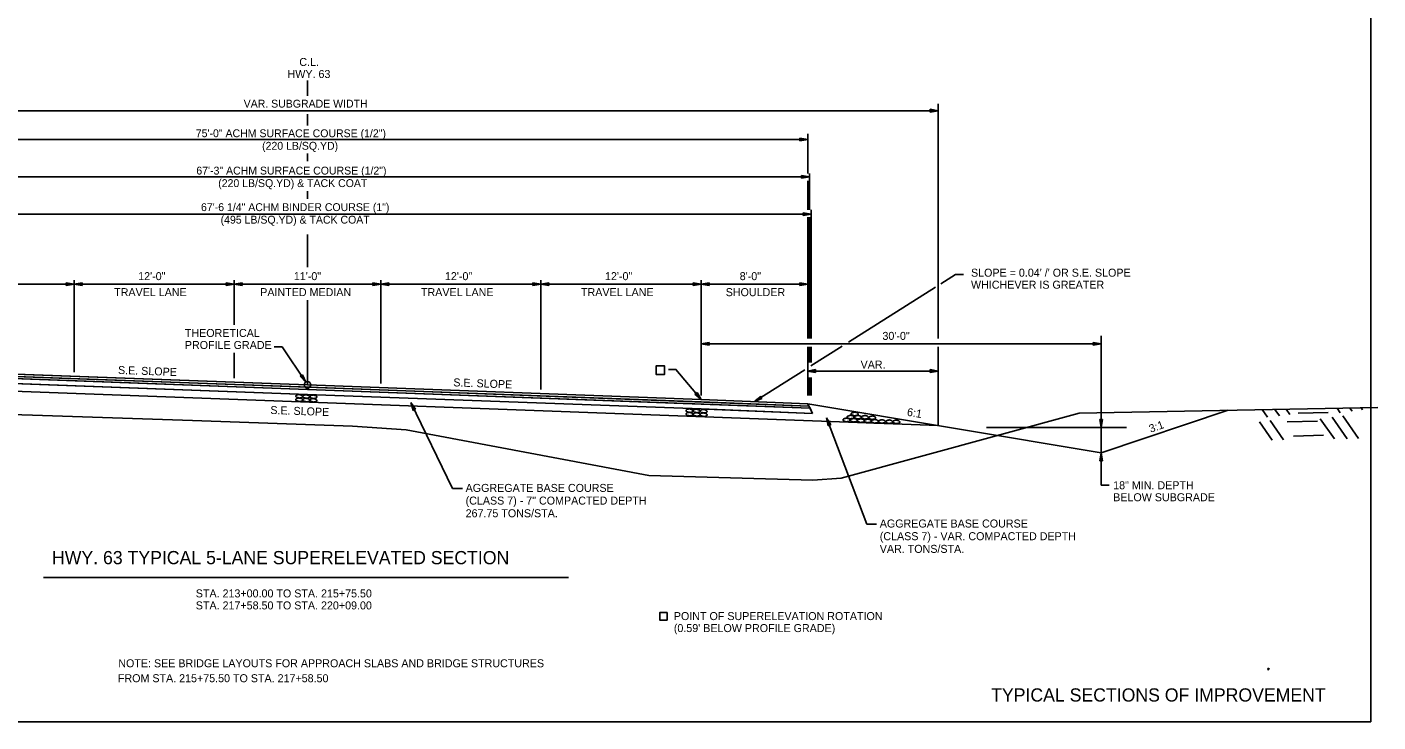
# Model space of a CAD drawing. Extents: x 1461846 to 1462006, y 1686171 to 1686805.
# Drawn here: x 1461905.1 to 1462006.4, y 1686568.7 to 1686620.8 of the extents above; entities that cross this region are included whole.
import ezdxf

# ---------------------------------------------------------------- set-up
doc = ezdxf.new("R2010")
doc.units = 0
for name, color, linetype in [('1', 7, 'Continuous'), ('10', 7, 'Continuous'), ('12', 7, 'Continuous'), ('19', 7, 'Continuous'), ('20', 7, 'Continuous'), ('3', 7, 'Continuous'), ('NO PLOT CELL', 7, 'Continuous'), ('R_Draft', 7, 'Continuous')]:
    doc.layers.add(name, color=color, linetype=linetype)

# ---------------------------------------------------------------- blocks, each defined once
blk = doc.blocks.new('ROCKS')
at = {"layer": '1'}
blk.add_spline([(0.013, 0.06), (0.053, 0.053), (0.107, 0.033), (0.133, 0.013), (0.133, -0.007), (0.12, -0.033), (0.107, -0.04), (0.073, -0.053), (0.033, -0.067), (0.013, -0.067), (-0.02, -0.06), (-0.06, -0.053), (-0.087, -0.047), (-0.113, -0.02), (-0.113, -0.007), (-0.107, 0.02), (-0.087, 0.033), (-0.067, 0.047), (-0.033, 0.053), (-0.02, 0.06), (0.013, 0.06)], degree=3, dxfattribs=at)

msp = doc.modelspace()

# ---------------------------------------------------------------- linework, layer by layer
at = {"layer": '10'}
for p, q in [((1462005.89, 1686568.71), (1462005.89, 1686666.54)), ((1461846.35, 1686568.71), (1462005.89, 1686568.71))]:
    msp.add_line(p, q, dxfattribs=at)
msp.add_lwpolyline([(1461952.31, 1686594.77), (1461952.95, 1686594.77), (1461952.95, 1686595.41), (1461952.31, 1686595.41), (1461952.31, 1686594.77)], dxfattribs=at)
at = {"layer": '19'}
for p, q in [((1461973.45, 1686597.47), (1461973.45, 1686615.07)), ((1461876.76, 1686614.55), (1461973.45, 1686614.55)), ((1461972.85, 1686614.45), (1461972.85, 1686614.66)), ((1461972.85, 1686614.66), (1461973.45, 1686614.55)), ((1461972.85, 1686614.6), (1461973.29, 1686614.57)), ((1461973.45, 1686614.55), (1461972.85, 1686614.45)), ((1461973.29, 1686614.54), (1461972.85, 1686614.5)), ((1461963.68, 1686609.84), (1461963.68, 1686612.81)), ((1461888.68, 1686612.38), (1461963.68, 1686612.38)), ((1461963.08, 1686612.28), (1461963.08, 1686612.49)), ((1461963.08, 1686612.49), (1461963.68, 1686612.38)), ((1461963.08, 1686612.43), (1461963.52, 1686612.4)), ((1461963.68, 1686612.38), (1461963.08, 1686612.28)), ((1461963.52, 1686612.37), (1461963.08, 1686612.33)), ((1461963.68, 1686607.11), (1461963.68, 1686609.29)), ((1461963.68, 1686597.47), (1461963.68, 1686606.56)), ((1461963.68, 1686593.19), (1461963.68, 1686596.83)), ((1461973.45, 1686590.94), (1461973.45, 1686596.83)), ((1461937.05, 1686586.22), (1461933.92, 1686592.66)), ((1461934.1, 1686592.07), (1461933.92, 1686592.66)), ((1461933.92, 1686592.66), (1461934.28, 1686592.17)), ((1461934.14, 1686592.1), (1461933.98, 1686592.51)), ((1461934, 1686592.52), (1461934.23, 1686592.15)), ((1461963.68, 1686592.57), (1461964.04, 1686591.84)), ((1461934.28, 1686592.17), (1461934.1, 1686592.07)), ((1461964.04, 1686591.84), (1461963.85, 1686592.23)), ((1461963.85, 1686592.23), (1461963.85, 1686592.23)), ((1461964.04, 1686591.84), (1461964.04, 1686591.84)), ((1461968.1, 1686583.55), (1461965.09, 1686591.52)), ((1461965.2, 1686590.92), (1461965.09, 1686591.52)), ((1461965.09, 1686591.52), (1461965.4, 1686590.99)), ((1461998.15, 1686591.56), (1461997.76, 1686592.13)), ((1461999.04, 1686591.67), (1461998.7, 1686592.15)), ((1461999.83, 1686591.77), (1461999.56, 1686592.16)), ((1462002.71, 1686591.91), (1462000.45, 1686591.86)), ((1462004.12, 1686589.95), (1462002.99, 1686591.56)), ((1462003.6, 1686591.9), (1462003.36, 1686592.24)), ((1462004.97, 1686589.96), (1462003.79, 1686591.66)), ((1462004.49, 1686592.01), (1462004.32, 1686592.25)), ((1462005.28, 1686592.12), (1462005.17, 1686592.27)), ((1461965.25, 1686590.94), (1461965.13, 1686591.36)), ((1461965.16, 1686591.37), (1461965.35, 1686590.98)), ((1461965.4, 1686590.99), (1461965.2, 1686590.92)), ((1461998.51, 1686589.85), (1461997.55, 1686591.21)), ((1461999.36, 1686589.86), (1461998.34, 1686591.32)), ((1462001.89, 1686591.27), (1461999.62, 1686591.21)), ((1462003.16, 1686589.93), (1462002.1, 1686591.45)), ((1462002.35, 1686590.21), (1462000.09, 1686590.14)), ((1461937.79, 1686586.22), (1461937.05, 1686586.22)), ((1461968.84, 1686583.55), (1461968.1, 1686583.55))]:
    msp.add_line(p, q, dxfattribs=at)
for points in [[(1461888.59, 1686595.2), (1461901.59, 1686594.72), (1461926.18, 1686593.81), (1461955.68, 1686592.72), (1461963.76, 1686592.4), (1461963.68, 1686592.57), (1461955.68, 1686592.89), (1461926.18, 1686593.98), (1461901.55, 1686594.89), (1461888.68, 1686595.37)], [(1461896.51, 1686594.74), (1461907.59, 1686594.33), (1461926.17, 1686593.65), (1461955.9, 1686592.55), (1461963.85, 1686592.23), (1461963.85, 1686592.23), (1461963.76, 1686592.4), (1461963.76, 1686592.4), (1461926.32, 1686593.81), (1461907.55, 1686594.5), (1461896.59, 1686594.91)]]:
    msp.add_lwpolyline(points, close=True, dxfattribs=at)
for points in [[(1461963.85, 1686592.23), (1461955.68, 1686592.55), (1461926.17, 1686593.65), (1461896.84, 1686594.73), (1461896.51, 1686594.74)], [(1461896.33, 1686594.38), (1461896.82, 1686594.36), (1461926.18, 1686593.27), (1461955.68, 1686592.18), (1461964.04, 1686591.84)]]:
    msp.add_lwpolyline(points, dxfattribs=at)
at = {"layer": '20'}
for p, q in [((1461926.18, 1686610.77), (1461926.18, 1686611.34)), ((1461963.8, 1686607.11), (1461963.8, 1686609.84)), ((1461963.8, 1686609.58), (1461896.55, 1686609.58)), ((1461963.2, 1686609.48), (1461963.2, 1686609.69)), ((1461963.2, 1686609.69), (1461963.8, 1686609.58)), ((1461963.2, 1686609.63), (1461963.64, 1686609.6)), ((1461963.8, 1686609.58), (1461963.2, 1686609.48)), ((1461963.64, 1686609.57), (1461963.2, 1686609.53)), ((1461926.18, 1686607.95), (1461926.18, 1686608.52)), ((1461963.93, 1686606.78), (1461896.41, 1686606.78)), ((1461963.33, 1686606.68), (1461963.33, 1686606.89)), ((1461963.33, 1686606.89), (1461963.93, 1686606.78)), ((1461963.33, 1686606.83), (1461963.77, 1686606.8)), ((1461963.93, 1686606.78), (1461963.33, 1686606.68)), ((1461963.77, 1686606.77), (1461963.33, 1686606.73)), ((1461963.93, 1686601.17), (1461963.93, 1686607.11)), ((1461963.8, 1686601.17), (1461963.8, 1686606.56)), ((1461963.8, 1686597.47), (1461963.8, 1686601.17)), ((1461963.93, 1686597.47), (1461963.93, 1686601.17)), ((1461963.8, 1686595.67), (1461963.8, 1686596.83)), ((1461963.93, 1686595.67), (1461963.93, 1686596.83)), ((1461964.27, 1686595.13), (1461963.67, 1686595.02)), ((1461963.67, 1686595.02), (1461973.45, 1686595.02)), ((1461963.67, 1686595.02), (1461964.27, 1686594.92)), ((1461963.8, 1686593.19), (1461963.8, 1686594.55)), ((1461964.27, 1686595.07), (1461963.83, 1686595.04)), ((1461963.83, 1686595.01), (1461964.27, 1686594.97)), ((1461963.93, 1686593.19), (1461963.93, 1686594.55)), ((1461964.27, 1686594.92), (1461964.27, 1686595.13)), ((1461972.85, 1686595.13), (1461972.85, 1686594.92)), ((1461973.45, 1686595.02), (1461972.85, 1686595.13)), ((1461973.29, 1686595.04), (1461972.85, 1686595.07)), ((1461972.85, 1686594.92), (1461973.45, 1686595.02)), ((1461972.85, 1686594.97), (1461973.29, 1686595.01))]:
    msp.add_line(p, q, dxfattribs=at)
at = {"layer": '3'}
msp.add_line((1461906.38, 1686579.55), (1461945.74, 1686579.55), dxfattribs=at)
at = {"layer": 'NO PLOT CELL'}
msp.add_circle((1461998.22, 1686572.68), 0.05, dxfattribs=at)
at = {"layer": 'R_Draft'}
for p, q in [((1461926.18, 1686615.67), (1461926.18, 1686616.81)), ((1461926.18, 1686613.45), (1461926.18, 1686614.28)), ((1461926.18, 1686602.81), (1461926.18, 1686605.27)), ((1461908.08, 1686601.64), (1461908.08, 1686601.43)), ((1461908.68, 1686601.54), (1461908.08, 1686601.64)), ((1461908.68, 1686594.93), (1461908.68, 1686601.84)), ((1461908.68, 1686601.54), (1461909.28, 1686601.64)), ((1461909.28, 1686601.64), (1461909.28, 1686601.43)), ((1461920.08, 1686601.64), (1461920.08, 1686601.43)), ((1461920.68, 1686601.54), (1461920.08, 1686601.64)), ((1461920.68, 1686598.48), (1461920.68, 1686601.84)), ((1461920.68, 1686601.54), (1461921.28, 1686601.64)), ((1461921.28, 1686601.64), (1461921.28, 1686601.43)), ((1461931.08, 1686601.64), (1461931.08, 1686601.43)), ((1461931.68, 1686601.54), (1461931.08, 1686601.64)), ((1461931.68, 1686594.08), (1461931.68, 1686601.84)), ((1461931.68, 1686601.54), (1461932.28, 1686601.64)), ((1461932.28, 1686601.64), (1461932.28, 1686601.43)), ((1461943.08, 1686601.64), (1461943.08, 1686601.43)), ((1461943.68, 1686601.54), (1461943.08, 1686601.64)), ((1461943.68, 1686593.63), (1461943.68, 1686601.84)), ((1461943.68, 1686601.54), (1461944.28, 1686601.64)), ((1461944.28, 1686601.64), (1461944.28, 1686601.43)), ((1461955.08, 1686601.43), (1461955.08, 1686601.64)), ((1461955.08, 1686601.64), (1461955.68, 1686601.54)), ((1461955.68, 1686593.19), (1461955.68, 1686601.84)), ((1461955.68, 1686601.54), (1461956.28, 1686601.64)), ((1461956.28, 1686601.64), (1461956.28, 1686601.43)), ((1461963.08, 1686601.43), (1461963.08, 1686601.64)), ((1461963.08, 1686601.64), (1461963.68, 1686601.54)), ((1461963.68, 1686597.47), (1461963.68, 1686601.84)), ((1461896.68, 1686601.54), (1461908.68, 1686601.54)), ((1461908.52, 1686601.55), (1461908.08, 1686601.59)), ((1461908.08, 1686601.43), (1461908.68, 1686601.54)), ((1461908.08, 1686601.48), (1461908.52, 1686601.52)), ((1461908.68, 1686601.54), (1461920.68, 1686601.54)), ((1461909.28, 1686601.43), (1461908.68, 1686601.54)), ((1461908.84, 1686601.55), (1461909.28, 1686601.59)), ((1461909.28, 1686601.48), (1461908.84, 1686601.52)), ((1461920.52, 1686601.55), (1461920.08, 1686601.59)), ((1461920.08, 1686601.43), (1461920.68, 1686601.54)), ((1461920.08, 1686601.48), (1461920.52, 1686601.52)), ((1461921.28, 1686601.43), (1461920.68, 1686601.54)), ((1461920.68, 1686601.54), (1461931.68, 1686601.54)), ((1461920.84, 1686601.55), (1461921.28, 1686601.59)), ((1461921.28, 1686601.48), (1461920.84, 1686601.52)), ((1461931.52, 1686601.55), (1461931.08, 1686601.59)), ((1461931.08, 1686601.43), (1461931.68, 1686601.54)), ((1461931.08, 1686601.48), (1461931.52, 1686601.52)), ((1461932.28, 1686601.43), (1461931.68, 1686601.54)), ((1461943.68, 1686601.54), (1461931.68, 1686601.54)), ((1461931.84, 1686601.55), (1461932.28, 1686601.59)), ((1461932.28, 1686601.48), (1461931.84, 1686601.52)), ((1461943.52, 1686601.55), (1461943.08, 1686601.59)), ((1461943.08, 1686601.43), (1461943.68, 1686601.54)), ((1461943.08, 1686601.48), (1461943.52, 1686601.52)), ((1461955.68, 1686601.54), (1461943.68, 1686601.54)), ((1461944.28, 1686601.43), (1461943.68, 1686601.54)), ((1461943.84, 1686601.55), (1461944.28, 1686601.59)), ((1461944.28, 1686601.48), (1461943.84, 1686601.52)), ((1461955.08, 1686601.59), (1461955.52, 1686601.55)), ((1461955.68, 1686601.54), (1461955.08, 1686601.43)), ((1461955.52, 1686601.52), (1461955.08, 1686601.48)), ((1461963.68, 1686601.54), (1461955.68, 1686601.54)), ((1461956.28, 1686601.43), (1461955.68, 1686601.54)), ((1461955.84, 1686601.55), (1461956.28, 1686601.59)), ((1461956.28, 1686601.48), (1461955.84, 1686601.52)), ((1461963.08, 1686601.59), (1461963.52, 1686601.55)), ((1461963.68, 1686601.54), (1461963.08, 1686601.43)), ((1461963.52, 1686601.52), (1461963.08, 1686601.48)), ((1461926.18, 1686593.98), (1461926.18, 1686600.34)), ((1461985.68, 1686590.73), (1461985.68, 1686597.66)), ((1461955.68, 1686597.06), (1461956.28, 1686597.17)), ((1461985.68, 1686597.06), (1461955.68, 1686597.06)), ((1461956.28, 1686596.96), (1461955.68, 1686597.06)), ((1461955.84, 1686597.08), (1461956.28, 1686597.11)), ((1461956.28, 1686597.01), (1461955.84, 1686597.05)), ((1461956.28, 1686597.17), (1461956.28, 1686596.96)), ((1461985.08, 1686596.96), (1461985.08, 1686597.17)), ((1461985.08, 1686597.17), (1461985.68, 1686597.06)), ((1461985.08, 1686597.11), (1461985.52, 1686597.08)), ((1461985.68, 1686597.06), (1461985.08, 1686596.96)), ((1461985.52, 1686597.05), (1461985.08, 1686597.01)), ((1461920.68, 1686594.48), (1461920.68, 1686596.38)), ((1461925.8, 1686594.75), (1461925.63, 1686594.63)), ((1461925.63, 1686594.63), (1461926.04, 1686594.19)), ((1461925.67, 1686594.66), (1461925.94, 1686594.32)), ((1461925.96, 1686594.33), (1461925.76, 1686594.72)), ((1461926.04, 1686594.19), (1461925.8, 1686594.75)), ((1461955.38, 1686593.42), (1461955.22, 1686593.29)), ((1461955.22, 1686593.29), (1461955.68, 1686592.89)), ((1461955.25, 1686593.31), (1461955.56, 1686593)), ((1461955.58, 1686593.02), (1461955.34, 1686593.38)), ((1461955.68, 1686592.89), (1461955.38, 1686593.42)), ((1461963.68, 1686592.57), (1461955.68, 1686592.89)), ((1461963.76, 1686592.4), (1461955.68, 1686592.72)), ((1461955.84, 1686592.55), (1461955.68, 1686592.55)), ((1461963.85, 1686592.23), (1461955.84, 1686592.55)), ((1461959.68, 1686592.73), (1461960.13, 1686593.14)), ((1461960.24, 1686592.96), (1461959.68, 1686592.73)), ((1461959.8, 1686592.83), (1461960.15, 1686593.09)), ((1461960.21, 1686593.01), (1461959.82, 1686592.8)), ((1461960.13, 1686593.14), (1461960.24, 1686592.96)), ((1461985.68, 1686588.9), (1461963.68, 1686592.57)), ((1461956.03, 1686592.16), (1461955.68, 1686592.18)), ((1461964.04, 1686591.84), (1461956.03, 1686592.16)), ((1461995.2, 1686592.08), (1461985.68, 1686588.9)), ((1461977.07, 1686590.78), (1461987.58, 1686590.78)), ((1461985.78, 1686591.38), (1461985.57, 1686591.38)), ((1461985.57, 1686591.38), (1461985.68, 1686590.78)), ((1461985.62, 1686591.38), (1461985.66, 1686590.94)), ((1461985.68, 1686590.78), (1461985.78, 1686591.38)), ((1461985.68, 1686586.46), (1461985.68, 1686590.73)), ((1461985.69, 1686590.94), (1461985.73, 1686591.38)), ((1461985.68, 1686588.9), (1461985.57, 1686588.3)), ((1461985.66, 1686588.74), (1461985.63, 1686588.3)), ((1461985.78, 1686588.3), (1461985.68, 1686588.9)), ((1461985.73, 1686588.3), (1461985.69, 1686588.74)), ((1461985.57, 1686588.3), (1461985.78, 1686588.3)), ((1461986.28, 1686586.46), (1461985.68, 1686586.46))]:
    msp.add_line(p, q, dxfattribs=at)
for points in [[(1461975.35, 1686602.27), (1461974.75, 1686602.27), (1461973.65, 1686601.57)], [(1461973.25, 1686601.32), (1461966.74, 1686597.2)], [(1461923.67, 1686596.85), (1461924.27, 1686596.85), (1461926.04, 1686594.19)], [(1461966.27, 1686596.9), (1461963.91, 1686595.41)], [(1461955.68, 1686592.89), (1461926.18, 1686593.98), (1461896.68, 1686595.07)], [(1461955.68, 1686592.72), (1461926.18, 1686593.81), (1461896.68, 1686594.9)], [(1461955.68, 1686592.55), (1461926.18, 1686593.65), (1461896.68, 1686594.74)], [(1461952.95, 1686594.77), (1461952.95, 1686595.41), (1461952.31, 1686595.41), (1461952.31, 1686594.77), (1461952.95, 1686594.77)], [(1461953.23, 1686595.15), (1461953.8, 1686595.15), (1461955.68, 1686592.89)], [(1461963.45, 1686595.12), (1461959.68, 1686592.73)], [(1461955.68, 1686592.18), (1461926.18, 1686593.27), (1461896.68, 1686594.36)], [(1461973.45, 1686590.94), (1461896.68, 1686593.78)], [(1462006.43, 1686592.29), (1461984.04, 1686591.86), (1461966.18, 1686586.99), (1461964.05, 1686586.83), (1461959.64, 1686586.97), (1461951.76, 1686587.2), (1461933.56, 1686590.62), (1461929.56, 1686590.9), (1461917.56, 1686591.31), (1461905.56, 1686591.72), (1461901.56, 1686591.84), (1461888.13, 1686588.11)], [(1461953.14, 1686576.35), (1461953.14, 1686576.91), (1461952.58, 1686576.91), (1461952.58, 1686576.35), (1461953.14, 1686576.35)]]:
    msp.add_lwpolyline(points, dxfattribs=at)
msp.add_circle((1461926.17, 1686593.98), 0.25, dxfattribs=at)

# ---------------------------------------------------------------- block references
at = {"layer": '19'}
for p, xscale, yscale, rotation in [((1461925.54, 1686593.14), 2.0611362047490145, 2.0611362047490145, -4.232447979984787), ((1461925.54, 1686592.88), 2.0611362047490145, 2.0611362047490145, -4.232447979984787), ((1461926.07, 1686593.12), 2.0611362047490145, 2.0611362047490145, -4.232447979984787), ((1461926.07, 1686592.86), 2.0611362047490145, 2.0611362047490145, -4.232447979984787), ((1461926.6, 1686593.1), 2.0611362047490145, 2.0611362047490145, -4.232447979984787), ((1461926.6, 1686592.84), 2.0611362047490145, 2.0611362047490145, -4.232447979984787), ((1461954.8, 1686591.8), 2.0611362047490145, 2.0611362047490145, -4.232447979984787), ((1461954.8, 1686592.06), 2.0611362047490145, 2.0611362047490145, -4.232447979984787), ((1461955.33, 1686591.78), 2.0611362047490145, 2.0611362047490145, -4.232447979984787), ((1461955.33, 1686592.04), 2.0611362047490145, 2.0611362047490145, -4.232447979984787), ((1461955.86, 1686592.02), 2.0611362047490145, 2.0611362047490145, -4.232447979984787), ((1461955.86, 1686591.76), 2.0611362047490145, 2.0611362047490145, -4.232447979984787), ((1461966.6, 1686591.36), 2.061136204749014, -2.061136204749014, 178.63717054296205), ((1461966.91, 1686591.58), 2.061136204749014, -2.061136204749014, 178.63717054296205), ((1461967.22, 1686591.81), 2.061136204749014, -2.061136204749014, 178.63717054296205), ((1461967.46, 1686591.57), 2.061136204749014, -2.061136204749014, 178.63717054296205), ((1461967.99, 1686591.56), 2.061136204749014, -2.061136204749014, 178.63717054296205), ((1461968.53, 1686591.53), 2.061136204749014, -2.061136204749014, 178.63717054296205), ((1461967.15, 1686591.34), 2.061136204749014, -2.061136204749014, 178.63717054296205), ((1461967.68, 1686591.31), 2.061136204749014, -2.061136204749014, 178.63717054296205), ((1461968.2, 1686591.29), 2.061136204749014, -2.061136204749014, 178.63717054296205), ((1461968.73, 1686591.26), 2.061136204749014, -2.061136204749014, 178.63717054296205), ((1461969.26, 1686591.25), 2.061136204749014, -2.061136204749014, 178.63717054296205), ((1461969.8, 1686591.23), 2.061136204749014, -2.061136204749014, 178.63717054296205), ((1461970.34, 1686591.22), 2.061136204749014, -2.061136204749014, 178.63717054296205)]:
    msp.add_blockref('ROCKS', p, dxfattribs=dict(at, xscale=xscale, yscale=yscale, rotation=rotation))

# ---------------------------------------------------------------- texts
at = {"layer": '10'}
for s, p in [('STA. 213+00.00 TO STA. 215+75.50', (1461917.8, 1686578.05)), ('STA. 217+58.50 TO STA. 220+09.00', (1461917.8, 1686577.15)), ('FROM STA. 215+75.50 TO STA. 217+58.50', (1461911.96, 1686571.69))]:
    msp.add_text(s, height=0.6, rotation=359.9954, dxfattribs=at).set_placement(p)
msp.add_text('NOTE: SEE BRIDGE LAYOUTS FOR APPROACH SLABS AND BRIDGE STRUCTURES', height=0.6, dxfattribs=at).set_placement((1461911.99, 1686572.81))
at = {"layer": '12'}
msp.add_text('HWY. 63 TYPICAL 5-LANE SUPERELEVATED SECTION', height=0.99, rotation=359.9954, dxfattribs=at).set_placement((1461907.02, 1686580.54))
at = {"layer": '19'}
for s, p in [('VAR. SUBGRADE WIDTH', (1461921.39, 1686614.78)), ('75\'-0" ACHM SURFACE COURSE (1/2")', (1461917.8, 1686612.56)), ('(220 LB/SQ.YD)', (1461922.77, 1686611.62))]:
    msp.add_text(s, height=0.59, dxfattribs=at).set_placement(p)
for s, height, p in [('67\'-3" ACHM SURFACE COURSE (1/2")', 0.59, (1461917.84, 1686609.76)), ('(220 LB/SQ.YD) & TACK COAT', 0.59, (1461919.48, 1686608.82)), ('67\'-6 1/4" ACHM BINDER COURSE (1")', 0.59, (1461918.19, 1686607.02)), ('(495 LB/SQ.YD) & TACK COAT', 0.59, (1461919.66, 1686606.08)), ('AGGREGATE BASE COURSE', 0.6, (1461938.03, 1686585.96)), ('(CLASS 7) - 7" COMPACTED DEPTH', 0.6, (1461938.03, 1686585.01)), ('267.75 TONS/STA.', 0.6, (1461938.03, 1686584.06)), ('AGGREGATE BASE COURSE', 0.6, (1461969.08, 1686583.29)), ('(CLASS 7) - VAR. COMPACTED DEPTH', 0.6, (1461969.08, 1686582.34)), ('VAR. TONS/STA.', 0.6, (1461969.08, 1686581.39)), ('TYPICAL SECTIONS OF IMPROVEMENT', 0.99, (1461977.43, 1686570.24))]:
    msp.add_text(s, height=height, rotation=360, dxfattribs=at).set_placement(p)
at = {"layer": 'R_Draft'}
for s, rotation, p in [('C.L.', 360, (1461925.56, 1686617.9)), ('HWY. 63', 360, (1461924.68, 1686617)), ('VAR.', 360, (1461967.64, 1686595.21)), ('S.E. SLOPE', 357.881, (1461911.96, 1686594.81)), ('S.E. SLOPE', 357.881, (1461937.1, 1686593.88)), ('S.E. SLOPE', 357.881, (1461923.38, 1686591.81)), ('6:1', 350.5175, (1461971.09, 1686591.68)), ('3:1', 19.5057, (1461989.39, 1686590.39)), ('POINT OF SUPERELEVATION ROTATION', 359.9954, (1461953.64, 1686576.35)), ("(0.59' BELOW PROFILE GRADE)", 359.9954, (1461953.64, 1686575.45))]:
    msp.add_text(s, height=0.6, rotation=rotation, dxfattribs=at).set_placement(p)
for s, p in [("SLOPE = 0.04' /' OR S.E. SLOPE", (1461975.92, 1686602.1)), ('12\'-0"', (1461913.48, 1686601.84)), ('11\'-0"', (1461925.15, 1686601.84)), ('12\'-0"', (1461936.48, 1686601.84)), ('12\'-0"', (1461948.48, 1686601.84)), ('8\'-0"', (1461958.58, 1686601.84)), ('WHICHEVER IS GREATER', (1461975.92, 1686601.2)), ('TRAVEL LANE', (1461911.68, 1686600.64)), ('PAINTED MEDIAN', (1461922.63, 1686600.64)), ('TRAVEL LANE', (1461934.68, 1686600.64)), ('TRAVEL LANE', (1461946.68, 1686600.64)), ('SHOULDER', (1461957.53, 1686600.64)), ('THEORETICAL', (1461916.98, 1686597.58)), ('30\'-0"', (1461969.28, 1686597.36)), ('PROFILE GRADE', (1461916.98, 1686596.68)), ('18" MIN. DEPTH', (1461986.58, 1686586.16)), ('BELOW SUBGRADE', (1461986.58, 1686585.26))]:
    msp.add_text(s, height=0.6, dxfattribs=at).set_placement(p)

doc.saveas('drawing.dxf')
